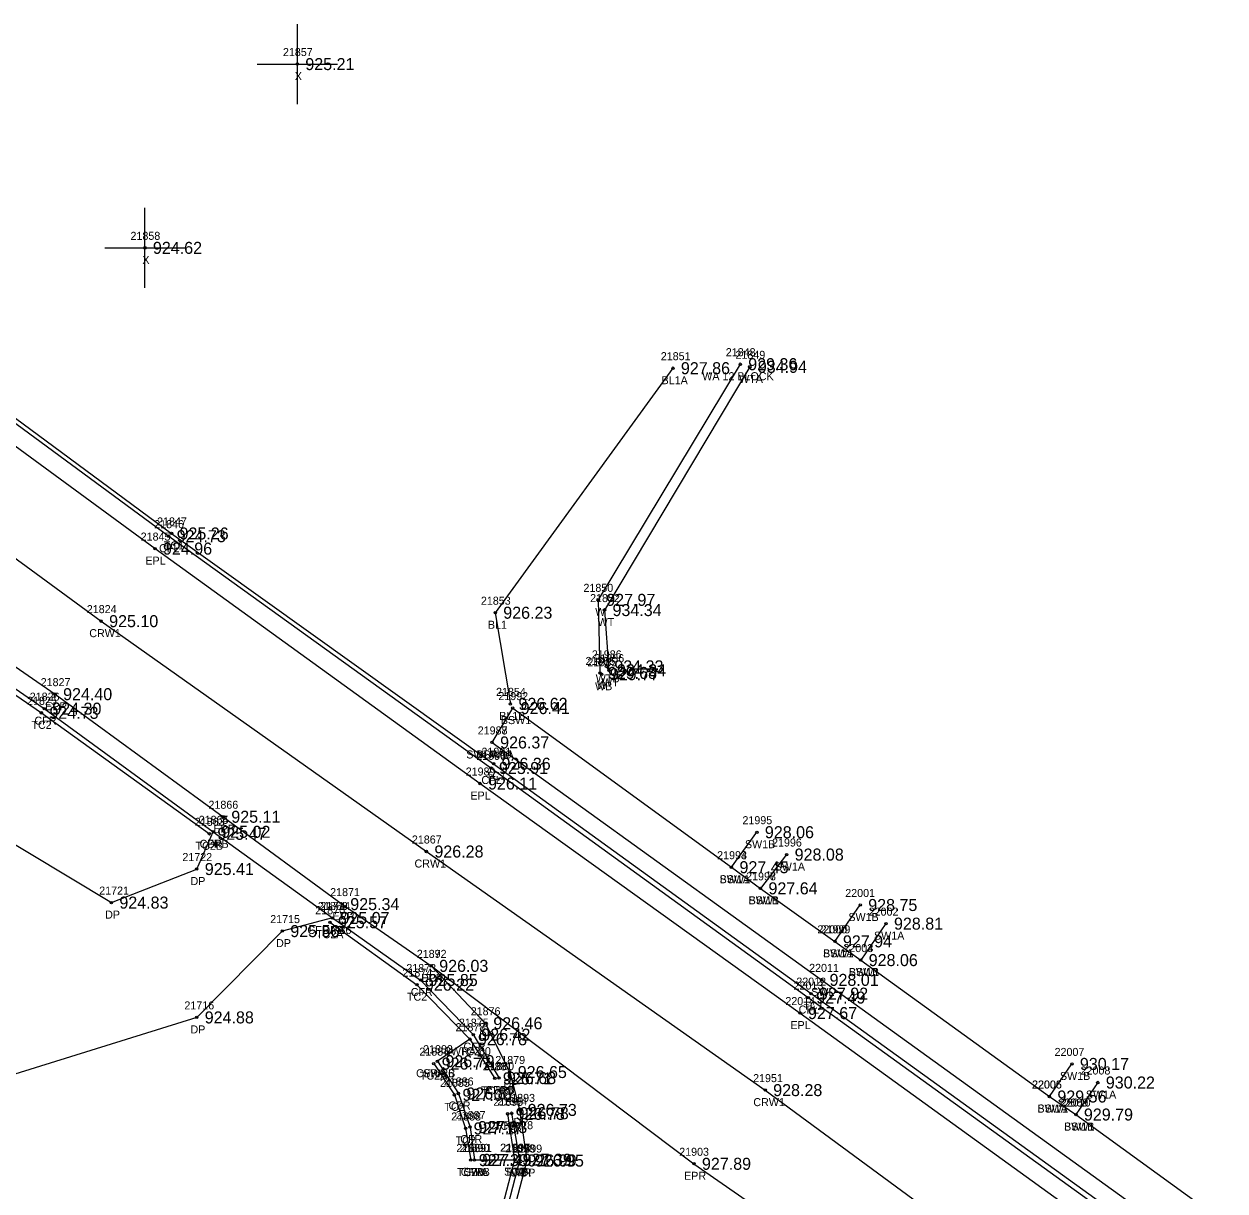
# Model space of a CAD drawing. Extents: x 1576181 to 1577685, y 1099396 to 1101490.
# Drawn here: x 1577294.3 to 1577444.3, y 1100935.6 to 1101081.3 of the extents above; entities that cross this region are included whole.
import ezdxf

# ---------------------------------------------------------------- set-up
doc = ezdxf.new("R2010")
doc.units = 0
for name, color, linetype in [('RD_DTM_BkLn1', 7, 'Continuous'), ('RD_DTM_BkLn2', 7, 'Continuous'), ('RD_DTM_BkLn_txCode', 7, 'Continuous'), ('RD_EX_BldgApp', 7, 'Continuous'), ('RD_EX_Conc', 7, 'Continuous'), ('RD_EX_Conc_txCode', 7, 'Continuous'), ('RD_EX_Driveway', 7, 'Continuous'), ('RD_EX_Driveway_txCode', 7, 'Continuous'), ('RD_EX_Misc', 7, 'Continuous'), ('RD_EX_Misc_txCode', 7, 'Continuous'), ('RD_EX_Road', 7, 'Continuous'), ('RD_EX_Road_txCode', 7, 'Continuous'), ('RD_EX_TX_Conc_ELEV', 7, 'Continuous'), ('RD_EX_TX_Driveway_ELEV', 7, 'Continuous'), ('RD_EX_TX_Misc_ELEV', 7, 'Continuous'), ('RD_EX_TX_Road_ELEV', 7, 'Continuous'), ('RD_HC_Survey_ELEV', 7, 'Continuous'), ('RD_HC_Survey_txCode', 7, 'Continuous'), ('RD_SMD_Locator', 7, 'Continuous')]:
    doc.layers.add(name, color=color, linetype=linetype)

msp = doc.modelspace()

# ---------------------------------------------------------------- linework, layer by layer
at = {"layer": 'RD_DTM_BkLn1'}
for points in [[(1577238.59, 1101054.64), (1577263.64, 1101036.24), (1577303.95, 1101006.72), (1577344.58, 1100977.95), (1577386.9, 1100948.15), (1577426.17, 1100919.26), (1577465.69, 1100889.09), (1577507.94, 1100862.82), (1577553.41, 1100842.12), (1577599.84, 1100824.14), (1577646.74, 1100805.8)], [(1577375.37, 1101038.31), (1577353.18, 1101007.77), (1577355.08, 1100996.39)]]:
    msp.add_lwpolyline(points, dxfattribs=at)
at = {"layer": 'RD_DTM_BkLn2'}
for points in [[(1577260.56, 1101056.27), (1577271.65, 1101048), (1577312.74, 1101017.67), (1577352.97, 1100988.91), (1577392.63, 1100960.2), (1577433.92, 1100930.47), (1577452.73, 1100916.9), (1577458.15, 1100912.82)], [(1577384.98, 1101038.48), (1577366.83, 1101008.1), (1577367.39, 1101000.59), (1577367.06, 1101001.07)], [(1577246.74, 1101029.36), (1577254.79, 1101023.97), (1577296.49, 1100995.27), (1577317.47, 1100980.16)], [(1577332.53, 1100969.12), (1577343.39, 1100961.32), (1577350.02, 1100954.51), (1577353.13, 1100949.61)], [(1577345.49, 1100951.46), (1577348.08, 1100947.56), (1577349.48, 1100943.36), (1577350.12, 1100939.41)], [(1577354.73, 1100945.19), (1577355.6, 1100939.46), (1577353.33, 1100930.81), (1577346.83, 1100920.55), (1577325.37, 1100889.7)]]:
    msp.add_lwpolyline(points, dxfattribs=at)
at = {"layer": 'RD_EX_BldgApp'}
msp.add_lwpolyline([(1577383.78, 1101038.81), (1577366.04, 1101009.38), (1577366.25, 1101000.25), (1577366.49, 1101000.09)], dxfattribs=at)
at = {"layer": 'RD_EX_Conc'}
for p, q in [((1577382.69, 1100975.99), (1577385.86, 1100980.36)), ((1577389.58, 1100977.57), (1577386.31, 1100973.35)), ((1577395.61, 1100966.73), (1577398.77, 1100971.27)), ((1577401.99, 1100968.94), (1577398.83, 1100964.39)), ((1577350.02, 1100954.51), (1577345.96, 1100951.76)), ((1577422.4, 1100947.35), (1577425.21, 1100951.42)), ((1577428.45, 1100949.1), (1577425.71, 1100945.1)), ((1577350.57, 1100939.44), (1577355.6, 1100939.46))]:
    msp.add_line(p, q, dxfattribs=at)
for points in [[(1577260.09, 1101055.74), (1577271.3, 1101047.57), (1577312.39, 1101017.33), (1577352.65, 1100988.38), (1577392.28, 1100959.71), (1577433.56, 1100929.93), (1577452.44, 1100916.35), (1577457.82, 1100912.39)], [(1577247, 1101029.77), (1577255.15, 1101024.5), (1577296.85, 1100995.79), (1577317.96, 1100980.41)], [(1577352.79, 1100991.57), (1577355.36, 1100995.86), (1577382.69, 1100975.99), (1577386.31, 1100973.35), (1577395.61, 1100966.73), (1577398.83, 1100964.39), (1577422.4, 1100947.35), (1577425.71, 1100945.1), (1577453.6, 1100924.89), (1577456.82, 1100922.74)], [(1577352.79, 1100991.57), (1577393.94, 1100961.92), (1577435.2, 1100932.14), (1577453.92, 1100918.67), (1577452.73, 1100916.9)], [(1577332.84, 1100969.65), (1577343.86, 1100961.9), (1577350.44, 1100955.08), (1577353.65, 1100949.66)], [(1577345.96, 1100951.76), (1577348.58, 1100947.73), (1577350.04, 1100943.53), (1577350.57, 1100939.44)], [(1577355.23, 1100945.27), (1577356.21, 1100939.37), (1577353.9, 1100930.52), (1577347.36, 1100920.27), (1577325.86, 1100889.36)]]:
    msp.add_lwpolyline(points, dxfattribs=at)
at = {"layer": 'RD_EX_Driveway'}
for points in [[(1577332.84, 1100969.65), (1577326.58, 1100968.01), (1577315.89, 1100957.23), (1577286.83, 1100948.19), (1577268.62, 1100949.98), (1577252.53, 1100957.02), (1577268.93, 1100993.4), (1577305.23, 1100971.57), (1577315.9, 1100975.76), (1577317.96, 1100980.41), (1577332.84, 1100969.65)], [(1577345.18, 1100963.67), (1577351.94, 1100956.5), (1577354.99, 1100950.41), (1577356.23, 1100945.68), (1577357.12, 1100939.35), (1577354.68, 1100929.98), (1577348.16, 1100919.82), (1577326.57, 1100888.92)]]:
    msp.add_lwpolyline(points, dxfattribs=at)
at = {"layer": 'RD_EX_Misc'}
for p, q in [((1577328.46, 1101071.29), (1577328.46, 1101081.29)), ((1577323.46, 1101076.29), (1577333.46, 1101076.29)), ((1577309.42, 1101048.34), (1577309.42, 1101058.34)), ((1577304.42, 1101053.34), (1577314.42, 1101053.34))]:
    msp.add_line(p, q, dxfattribs=at)
at = {"layer": 'RD_EX_Road'}
for points in [[(1577251.26, 1101061.34), (1577255.44, 1101056.29), (1577270.08, 1101045.56), (1577310.68, 1101015.78), (1577351.28, 1100986.44), (1577391.25, 1100957.77), (1577432.13, 1100928.26), (1577451.03, 1100914.55), (1577473.4, 1100898.43), (1577474.18, 1100899.6), (1577481.34, 1100895.67), (1577490.14, 1100894.7), (1577498.51, 1100899.09), (1577503.3, 1100907.84), (1577513.46, 1100934.77)], [(1577078.76, 1100718.33), (1577101.64, 1100758.92), (1577113.34, 1100780.09), (1577125.29, 1100804.69), (1577146.47, 1100851.25), (1577166.06, 1100897.32), (1577205.17, 1100988.68), (1577222.29, 1101028.96), (1577224.55, 1101032.02), (1577228.3, 1101034.47), (1577233.18, 1101036.1), (1577233.18, 1101036.1), (1577237.42, 1101035.84), (1577245.43, 1101032.85), (1577248.28, 1101031.55), (1577256.85, 1101026.16), (1577298.2, 1100997.6), (1577319.21, 1100982.29), (1577334.07, 1100971.38), (1577345.18, 1100963.67), (1577378, 1100938.95), (1577407.15, 1100918.71), (1577419.5, 1100910.06), (1577460.72, 1100880.37)]]:
    msp.add_lwpolyline(points, dxfattribs=at)
at = {"layer": 'RD_SMD_Locator'}
for centre in [(1577328.46, 1101076.29), (1577309.42, 1101053.34), (1577375.37, 1101038.31), (1577383.78, 1101038.81), (1577384.98, 1101038.48), (1577312.39, 1101017.33), (1577312.74, 1101017.67), (1577310.68, 1101015.78), (1577366.04, 1101009.38), (1577353.18, 1101007.77), (1577366.83, 1101008.1), (1577303.95, 1101006.72), (1577366.25, 1101000.25), (1577366.49, 1101000.09), (1577367.06, 1101001.07), (1577367.39, 1101000.59), (1577298.2, 1100997.6), (1577296.85, 1100995.79), (1577355.08, 1100996.39), (1577355.36, 1100995.86), (1577296.49, 1100995.27), (1577352.79, 1100991.57), (1577352.79, 1100991.57), (1577352.65, 1100988.38), (1577352.97, 1100988.91), (1577351.28, 1100986.44), (1577319.21, 1100982.29), (1577317.96, 1100980.41), (1577317.96, 1100980.41), (1577317.47, 1100980.16), (1577385.86, 1100980.36), (1577344.58, 1100977.95), (1577389.58, 1100977.57), (1577382.69, 1100975.99), (1577382.69, 1100975.99), (1577315.9, 1100975.76), (1577386.31, 1100973.35), (1577386.31, 1100973.35), (1577305.23, 1100971.57), (1577334.07, 1100971.38), (1577398.77, 1100971.27), (1577332.53, 1100969.12), (1577332.84, 1100969.65), (1577332.84, 1100969.65), (1577332.84, 1100969.65), (1577401.99, 1100968.94), (1577326.58, 1100968.01), (1577395.61, 1100966.73), (1577395.61, 1100966.73), (1577398.83, 1100964.39), (1577398.83, 1100964.39), (1577345.18, 1100963.67), (1577345.18, 1100963.67), (1577343.39, 1100961.32), (1577343.86, 1100961.9), (1577393.94, 1100961.92), (1577392.28, 1100959.71), (1577392.63, 1100960.2), (1577315.89, 1100957.23), (1577351.94, 1100956.5), (1577391.25, 1100957.77), (1577350.44, 1100955.08), (1577350.02, 1100954.51), (1577350.02, 1100954.51), (1577345.49, 1100951.46), (1577345.96, 1100951.76), (1577345.96, 1100951.76), (1577354.99, 1100950.41), (1577425.21, 1100951.42), (1577353.13, 1100949.61), (1577353.65, 1100949.66), (1577428.45, 1100949.1), (1577348.08, 1100947.56), (1577348.58, 1100947.73), (1577386.9, 1100948.15), (1577422.4, 1100947.35), (1577422.4, 1100947.35), (1577354.73, 1100945.19), (1577355.23, 1100945.27), (1577356.23, 1100945.68), (1577425.71, 1100945.1), (1577425.71, 1100945.1), (1577349.48, 1100943.36), (1577350.04, 1100943.53), (1577350.12, 1100939.41), (1577350.57, 1100939.44), (1577350.57, 1100939.44), (1577355.6, 1100939.46), (1577355.6, 1100939.46), (1577356.21, 1100939.37), (1577357.12, 1100939.35), (1577378, 1100938.95)]:
    msp.add_circle(centre, 0.15, dxfattribs=at)

# ---------------------------------------------------------------- texts
at = {"layer": 'RD_DTM_BkLn_txCode'}
for s, p in [('21851', (1577373.86, 1101039.31)), ('BL1A', (1577373.96, 1101036.31)), ('21853', (1577351.39, 1101008.77)), ('BL1', (1577352.26, 1101005.77)), ('21854', (1577353.28, 1100997.39)), ('BL1B', (1577353.68, 1100994.39))]:
    msp.add_text(s, height=1, dxfattribs=at).set_placement(p)
at = {"layer": 'RD_EX_Conc_txCode'}
for s, p in [('21847', (1577310.94, 1101018.67)), ('21846', (1577310.58, 1101018.33)), ('TC1', (1577311.78, 1101015.67)), ('CFL', (1577311.19, 1101015.33)), ('21825', (1577294.7, 1100996.27)), ('21826', (1577295.03, 1100996.79)), ('21992', (1577353.57, 1100996.86)), ('TC2', (1577295.25, 1100993.27)), ('CFR', (1577295.62, 1100993.79)), ('BSW1', (1577353.88, 1100993.86)), ('21987', (1577350.99, 1100992.57)), ('21988', (1577350.99, 1100992.57)), ('SWLA 60', (1577349.56, 1100989.57)), ('21990', (1577350.82, 1100989.38)), ('BSW1A', (1577350.82, 1100989.57)), ('21991', (1577351.46, 1100989.91)), ('CFL', (1577351.45, 1100986.38)), ('TC1', (1577352.01, 1100986.91)), ('21863', (1577315.65, 1100981.16)), ('21864', (1577316.14, 1100981.41)), ('21995', (1577384.06, 1100981.36)), ('TC2B', (1577315.75, 1100978.16)), ('CFRB', (1577316.25, 1100978.41)), ('SW1B', (1577384.37, 1100978.36)), ('21996', (1577387.76, 1100978.57)), ('21993', (1577380.9, 1100976.99)), ('21994', (1577380.9, 1100976.99)), ('SW1A', (1577388.08, 1100975.57)), ('SW1A', (1577381.2, 1100973.99)), ('BSW1', (1577381.21, 1100973.99)), ('21997', (1577384.52, 1100974.35)), ('21998', (1577384.52, 1100974.35)), ('22001', (1577396.9, 1100972.27)), ('21868', (1577331.03, 1100970.65)), ('SW1B', (1577384.83, 1100971.35)), ('BSW1', (1577384.83, 1100971.35)), ('21870', (1577330.7, 1100970.12)), ('SW1B', (1577397.29, 1100969.27)), ('22002', (1577399.83, 1100969.94)), ('CFRA 36', (1577329.72, 1100967.65)), ('22000', (1577393.42, 1100967.73)), ('21999', (1577393.82, 1100967.73)), ('TC2A', (1577330.8, 1100967.12)), ('SW1A', (1577400.49, 1100966.94)), ('SW1A', (1577394.12, 1100964.73)), ('BSW1', (1577394.13, 1100964.73)), ('22003', (1577396.67, 1100965.39)), ('22004', (1577396.67, 1100965.39)), ('21874', (1577341.59, 1100962.32)), ('21873', (1577342.07, 1100962.9)), ('22011', (1577392.39, 1100962.92)), ('SW1B', (1577397.35, 1100962.39)), ('BSW1', (1577397.35, 1100962.39)), ('22013', (1577390.45, 1100960.71)), ('22012', (1577390.79, 1100961.2)), ('TC2', (1577342.15, 1100959.32)), ('CFR', (1577342.63, 1100959.9)), ('SWL', (1577392.65, 1100959.92)), ('CFL', (1577391.08, 1100957.71)), ('TC1', (1577391.67, 1100958.2)), ('21875', (1577348.64, 1100956.08)), ('21877', (1577348.22, 1100955.51)), ('21878', (1577348.22, 1100955.51)), ('21882', (1577344.17, 1100952.76)), ('21883', (1577344.17, 1100952.76)), ('CFR', (1577349.21, 1100953.08)), ('21884', (1577343.7, 1100952.46)), ('SWRA 60', (1577346.76, 1100952.51)), ('TC2', (1577348.77, 1100952.51)), ('22007', (1577423.05, 1100952.42)), ('CFRA 6', (1577343.29, 1100949.76)), ('SWRB', (1577344.18, 1100949.76)), ('21881', (1577351.61, 1100950.61)), ('21880', (1577351.81, 1100950.66)), ('22008', (1577426.3, 1100950.1)), ('TC2A', (1577343.76, 1100949.46)), ('21885', (1577346.28, 1100948.56)), ('21886', (1577346.76, 1100948.73)), ('22006', (1577420.22, 1100948.35)), ('22005', (1577420.25, 1100948.35)), ('SW1B', (1577423.72, 1100949.42)), ('TC2B', (1577351.41, 1100947.61)), ('CFRB', (1577351.95, 1100947.66)), ('SW1A', (1577426.96, 1100947.1)), ('TC2', (1577346.83, 1100945.56)), ('CFR', (1577347.35, 1100945.73)), ('21895', (1577352.94, 1100946.19)), ('21894', (1577353.44, 1100946.27)), ('SW1A', (1577420.91, 1100945.35)), ('BSW1', (1577420.92, 1100945.35)), ('22009', (1577423.55, 1100946.1)), ('22010', (1577423.83, 1100946.1)), ('21888', (1577347.68, 1100944.36)), ('21887', (1577348.25, 1100944.53)), ('CFRA 18', (1577352.41, 1100943.27)), ('TC2A', (1577353, 1100943.19)), ('SW1B', (1577424.23, 1100943.1)), ('BSW1', (1577424.23, 1100943.1)), ('TC2', (1577348.23, 1100941.36)), ('CFR', (1577348.81, 1100941.53)), ('21889', (1577348.32, 1100940.41)), ('21890', (1577348.73, 1100940.44)), ('21891', (1577349.05, 1100940.44)), ('21896', (1577353.78, 1100940.46)), ('21897', (1577353.81, 1100940.46)), ('21898', (1577354.42, 1100940.37)), ('TC2B', (1577348.4, 1100937.41)), ('CFRB', (1577348.87, 1100937.44)), ('SWA', (1577349.24, 1100937.44)), ('SWB', (1577354.29, 1100937.46)), ('TC2', (1577354.36, 1100937.46)), ('CFR', (1577354.98, 1100937.37))]:
    msp.add_text(s, height=1, dxfattribs=at).set_placement(p)
at = {"layer": 'RD_EX_Driveway_txCode'}
for s, p in [('21865', (1577316.14, 1100981.41)), ('DP', (1577317.18, 1100978.41)), ('21722', (1577314.1, 1100976.76)), ('DP', (1577315.12, 1100973.76)), ('21721', (1577303.71, 1100972.57)), ('21869', (1577331.03, 1100970.65)), ('21714', (1577331.33, 1100970.65)), ('DP', (1577304.45, 1100969.57)), ('21715', (1577325.07, 1100969.01)), ('DPA', (1577331.58, 1100967.65)), ('DPB', (1577331.59, 1100967.65)), ('DP', (1577325.8, 1100966.01)), ('21872', (1577343.38, 1100964.67)), ('DPA', (1577343.91, 1100961.67)), ('21716', (1577314.35, 1100958.23)), ('21876', (1577350.12, 1100957.5)), ('DP', (1577315.11, 1100955.23)), ('DP', (1577351.16, 1100954.5)), ('21879', (1577353.19, 1100951.41)), ('DP', (1577354.21, 1100948.41)), ('21893', (1577354.43, 1100946.68)), ('DP', (1577355.45, 1100943.68)), ('21899', (1577355.32, 1100940.35)), ('DP', (1577356.34, 1100937.35))]:
    msp.add_text(s, height=1, dxfattribs=at).set_placement(p)
at = {"layer": 'RD_EX_Misc_txCode'}
for s, p in [('21857', (1577326.66, 1101077.29)), ('X', (1577328.14, 1101074.29)), ('21858', (1577307.62, 1101054.34)), ('X', (1577309.1, 1101051.34)), ('21848', (1577381.98, 1101039.81)), ('21849', (1577383.19, 1101039.48)), ('WA 12 BLOCK', (1577379.04, 1101036.81)), ('WTA', (1577383.64, 1101036.48)), ('21850', (1577364.2, 1101010.38)), ('21852', (1577365.03, 1101009.1)), ('W', (1577365.67, 1101007.38)), ('WT', (1577365.97, 1101006.1)), ('21986', (1577365.25, 1101002.07)), ('21855', (1577364.46, 1101001.25)), ('21985', (1577364.69, 1101001.09)), ('21856', (1577365.57, 1101001.59)), ('WTB', (1577365.73, 1100999.07)), ('WB', (1577365.65, 1100998.09)), ('W', (1577365.88, 1100998.25)), ('WT', (1577366.53, 1100998.59))]:
    msp.add_text(s, height=1, dxfattribs=at).set_placement(p)
at = {"layer": 'RD_EX_Road_txCode'}
for s, p in [('21845', (1577308.89, 1101016.78)), ('EPL', (1577309.48, 1101013.78)), ('21827', (1577296.4, 1100998.6)), ('EPR', (1577296.97, 1100995.6)), ('21989', (1577349.49, 1100987.44)), ('EPL', (1577350.08, 1100984.44)), ('21866', (1577317.36, 1100983.29)), ('EPR', (1577317.98, 1100980.29)), ('21871', (1577332.56, 1100972.38)), ('EPR', (1577332.85, 1100969.38)), ('21892', (1577343.38, 1100964.67)), ('EPR', (1577343.95, 1100961.67)), ('22014', (1577389.42, 1100958.77)), ('EPL', (1577390.05, 1100955.77)), ('21903', (1577376.16, 1100939.95)), ('EPR', (1577376.77, 1100936.95))]:
    msp.add_text(s, height=1, dxfattribs=at).set_placement(p)
at = {"layer": 'RD_EX_TX_Conc_ELEV'}
for s, p in [('924.73', (1577313.39, 1101016.58)), ('925.26', (1577313.74, 1101016.92)), ('924.73', (1577297.49, 1100994.52)), ('924.30', (1577297.85, 1100995.04)), ('926.41', (1577356.36, 1100995.11)), ('926.37', (1577353.79, 1100990.82)), ('926.37', (1577353.79, 1100990.82)), ('926.36', (1577353.97, 1100988.16)), ('925.91', (1577353.65, 1100987.63)), ('925.47', (1577318.47, 1100979.41)), ('925.02', (1577318.96, 1100979.66)), ('928.06', (1577386.86, 1100979.61)), ('928.08', (1577390.58, 1100976.82)), ('927.45', (1577383.69, 1100975.24)), ('927.45', (1577383.69, 1100975.24)), ('927.64', (1577387.31, 1100972.6)), ('927.64', (1577387.31, 1100972.6)), ('928.75', (1577399.77, 1100970.52)), ('925.07', (1577333.84, 1100968.9)), ('925.57', (1577333.53, 1100968.37)), ('928.81', (1577402.99, 1100968.19)), ('927.94', (1577396.61, 1100965.98)), ('927.94', (1577396.61, 1100965.98)), ('928.06', (1577399.83, 1100963.64)), ('928.06', (1577399.83, 1100963.64)), ('925.85', (1577344.86, 1100961.15)), ('928.01', (1577394.94, 1100961.17)), ('926.22', (1577344.39, 1100960.57)), ('927.49', (1577393.28, 1100958.96)), ('927.92', (1577393.63, 1100959.45)), ('926.78', (1577351.02, 1100953.76)), ('926.78', (1577351.02, 1100953.76)), ('926.42', (1577351.44, 1100954.33)), ('926.77', (1577346.49, 1100950.71)), ('926.79', (1577346.96, 1100951.01)), ('926.79', (1577346.96, 1100951.01)), ('930.17', (1577426.21, 1100950.67)), ('926.71', (1577354.13, 1100948.86)), ('926.68', (1577354.65, 1100948.91)), ('930.22', (1577429.45, 1100948.35)), ('927.00', (1577349.08, 1100946.81)), ('926.87', (1577349.58, 1100946.98)), ('929.56', (1577423.4, 1100946.6)), ('929.56', (1577423.4, 1100946.6)), ('926.78', (1577355.73, 1100944.44)), ('926.78', (1577356.23, 1100944.52)), ('929.79', (1577426.71, 1100944.35)), ('929.79', (1577426.71, 1100944.35)), ('927.17', (1577350.48, 1100942.61)), ('927.03', (1577351.04, 1100942.78)), ('927.39', (1577351.12, 1100938.66)), ('927.43', (1577351.57, 1100938.69)), ('927.43', (1577351.57, 1100938.69)), ('927.39', (1577356.6, 1100938.71)), ('927.39', (1577356.6, 1100938.71)), ('926.99', (1577357.21, 1100938.62))]:
    msp.add_text(s, height=1.5, dxfattribs=at).set_placement(p)
at = {"layer": 'RD_EX_TX_Driveway_ELEV'}
for s, p in [('925.02', (1577318.96, 1100979.66)), ('925.41', (1577316.9, 1100975.01)), ('924.83', (1577306.23, 1100970.82)), ('925.07', (1577333.84, 1100968.9)), ('925.07', (1577333.84, 1100968.9)), ('925.56', (1577327.58, 1100967.26)), ('926.03', (1577346.18, 1100962.92)), ('924.88', (1577316.89, 1100956.48)), ('926.46', (1577352.94, 1100955.75)), ('926.65', (1577355.99, 1100949.66)), ('926.73', (1577357.23, 1100944.93)), ('926.95', (1577358.12, 1100938.6))]:
    msp.add_text(s, height=1.5, dxfattribs=at).set_placement(p)
at = {"layer": 'RD_EX_TX_Misc_ELEV'}
for s, p in [('925.21', (1577329.46, 1101075.54)), ('924.62', (1577310.42, 1101052.59)), ('927.86', (1577376.37, 1101037.56)), ('929.36', (1577384.78, 1101038.06)), ('934.94', (1577385.98, 1101037.73)), ('927.97', (1577367.04, 1101008.63)), ('926.23', (1577354.18, 1101007.02)), ('934.34', (1577367.83, 1101007.35)), ('934.33', (1577368.06, 1101000.32)), ('929.68', (1577367.25, 1100999.5)), ('929.77', (1577367.49, 1100999.34)), ('934.34', (1577368.39, 1100999.84)), ('926.62', (1577356.08, 1100995.64))]:
    msp.add_text(s, height=1.5, dxfattribs=at).set_placement(p)
at = {"layer": 'RD_EX_TX_Road_ELEV'}
for s, p in [('924.96', (1577311.68, 1101015.03)), ('924.40', (1577299.2, 1100996.85)), ('926.11', (1577352.28, 1100985.69)), ('925.11', (1577320.21, 1100981.54)), ('925.34', (1577335.07, 1100970.63)), ('926.03', (1577346.18, 1100962.92)), ('927.67', (1577392.25, 1100957.02)), ('927.89', (1577379, 1100938.2))]:
    msp.add_text(s, height=1.5, dxfattribs=at).set_placement(p)
at = {"layer": 'RD_HC_Survey_ELEV'}
for s, p in [('925.10', (1577304.95, 1101005.97)), ('926.28', (1577345.58, 1100977.2)), ('928.28', (1577387.9, 1100947.4))]:
    msp.add_text(s, height=1.5, dxfattribs=at).set_placement(p)
at = {"layer": 'RD_HC_Survey_txCode'}
for s, p in [('21824', (1577302.16, 1101007.72)), ('CRW1', (1577302.47, 1101004.72)), ('21867', (1577342.77, 1100978.95)), ('CRW1', (1577343.1, 1100975.95)), ('21951', (1577385.39, 1100949.15)), ('CRW1', (1577385.42, 1100946.15))]:
    msp.add_text(s, height=1, dxfattribs=at).set_placement(p)

doc.saveas('drawing.dxf')
